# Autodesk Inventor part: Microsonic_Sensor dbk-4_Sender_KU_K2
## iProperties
Shininess: 20.0
Length Units: 11269
Angle Units: 11279
Time Units: 11290
Mass Units: 11283
Length Display Precision: 2
Angle Display Precision: 2
Part Number: Microsonic_Sensor dbk-4_Sender_KU_K2
Material: nicht zugewiesen
Document SubType Name: Modellieren
Description: dbk-4/Sender/KU/K2
Checked By: Alves
Created: 2005-08
Designer: Grube
Manufacturer: Standard
Standards Organization: Custom
Density: 0.0
Volumn: 0.0
Area: 0.0
PropertySet Name: Model Information
Control State: 0
Master: False
Checked Out: False
Last Check In By: Tanck
Last Check In Date: 2005-08-10
BESTELLNUMMER: dbk-4/Sender/KU/K2
ME: ST
Title: dbk-4 Sensoren
Author: Grube
Comments: keine Bemerkung
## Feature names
1. Grundfläche [Extrusion]
2. Vorderfläche [Extrusion]
3. Seitenkästen [Extrusion]
4. Innenfase [Chamfer]
5. Radius 0,2 innen [Fillet]
6. Radius 0,5 innen [Fillet]
7. Hinterfläche [Extrusion]
8. Ausschnitt Hinterfläche [Extrusion]
9. Zwischenstück [Extrusion]
10. Sensor [Hole]
11. Kabelmantel [Extrusion]
12. Kabellitze [Extrusion]
13. Radius 1 hinten [Fillet]
14. Radius 1 oben [Fillet]
15. Radius 1 außen [Fillet]
